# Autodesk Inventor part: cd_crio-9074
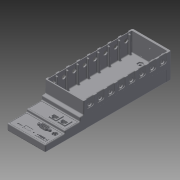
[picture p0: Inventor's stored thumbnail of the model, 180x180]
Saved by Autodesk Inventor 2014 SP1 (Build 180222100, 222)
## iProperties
Created: 2014-09
Part Number: cd_crio-9074
Material: Generic
Document SubType Name: Modeling
Designer: Michael
Density: 3.33216 g/cm^3
Appearance: Default
Mass: 272.252 g
Surface Area: 1824.41 cm^2
Volume: 272.252 cm^3
Author: chrisj
Title: CD_CRIO-9074
Creation Date: 2008-03-27
Sending System: PRO/ENGINEER BY PARAMETRIC TECHNOLOGY CORPORATION, 2006300
Preprocessor: PRO/ENGINEER BY PARAMETRIC TECHNOLOGY CORPORATION, 2006300
Author: Michael
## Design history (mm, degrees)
node "cd_crio-90741"
body "Solid1"
body "Solid2"
body "Solid3"
body "Solid4"
body "Solid5"
body "Solid6"
body "Solid7"
body "Solid8"
body "Solid9"
body "Solid10"
body "Solid11"
body "Solid12"
body "Solid13"
body "Solid14"
body "Solid15"
body "Solid16"
body "Solid17"
body "Solid18"
body "Solid19"
body "Solid20"
body "Solid21"
body "Solid22"
body "Solid23"
body "Solid24"
body "Solid25"
body "Solid26"
body "Solid27"
body "Solid28"
body "Solid29"
body "Solid30"
body "Solid31"
body "Solid32"
body "Solid33"
body "Solid34"
body "Solid35"
body "Solid36"
body "Solid37"
body "Solid38"
body "Solid39"
body "Solid40"
body "Solid41"
body "Solid42"
body "Solid43"
node "Base1"
node "Base2"
node "Base3"
node "Base4"
node "Base5"
node "Base6"
node "Base7"
node "Base8"
node "Base9"
node "Base10"
node "Base11"
node "Base12"
node "Base13"
node "Base14"
node "Base15"
node "Base16"
node "Base17"
node "Base18"
node "Base19"
node "Base20"
node "Base21"
node "Base22"
node "Base23"
node "Base24"
node "Base25"
node "Base26"
node "Base27"
node "Base28"
node "Base29"
node "Base30"
node "Base31"
node "Base32"
node "Base33"
node "Base34"
node "Base35"
node "Base36"
node "Base37"
node "Base38"
node "Base39"
node "Base40"
node "Base41"
node "Base42"
node "Base43"
